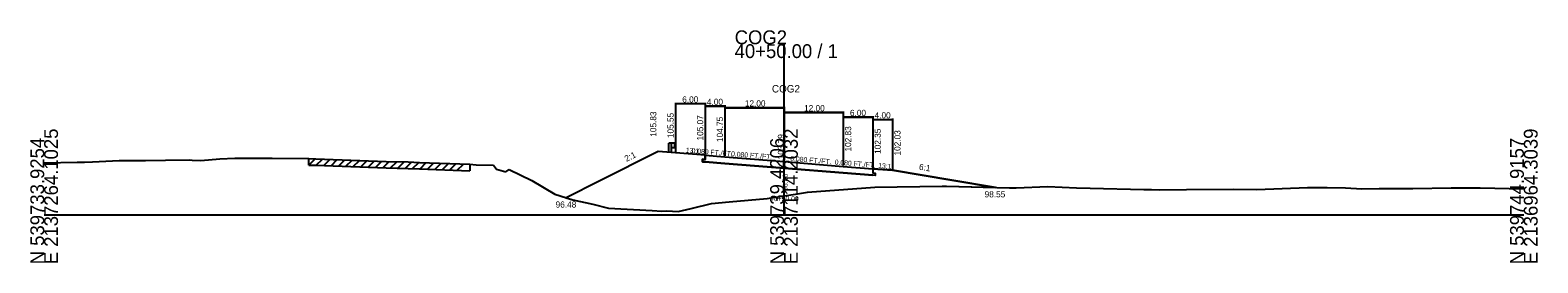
# Model space of a CAD drawing. Extents: x -13397 to 2303, y -10 to 39059.
# Drawn here: x 997.2 to 1302.8, y 20990.3 to 21037.4 of the extents above; entities that cross this region are included whole.
import ezdxf

# ---------------------------------------------------------------- set-up
doc = ezdxf.new("R2010")
doc.units = 0
for name, color, linetype in [('Level 1', 7, 'Continuous'), ('Level 5', 7, 'Continuous'), ('Level 53', 7, 'Continuous'), ('Level 54', 7, 'Continuous'), ('Level 55', 7, 'Continuous'), ('Level 7', 7, 'Continuous'), ('RD_GPK_XS_Cell', 7, 'Continuous'), ('RD_XS_EwShp', 7, 'Continuous'), ('RD_XS_ExGround', 7, 'Continuous'), ('RD_XS_ExPaveRet', 7, 'Continuous'), ('RD_XS_Pave', 7, 'Continuous'), ('RD_XS_TX_Baseline', 7, 'Continuous'), ('RD_XS_TX_Elev_EX', 7, 'Continuous'), ('RD_XS_TX_Elev_PR', 7, 'Continuous'), ('RD_XS_TX_Station', 7, 'Continuous')]:
    doc.layers.add(name, color=color, linetype=linetype)

msp = doc.modelspace()

# ---------------------------------------------------------------- linework, layer by layer
at = {"layer": 'Level 1'}
for p, q in [((1126.66, 21012.55), (1126.66, 21014.54)), ((1127.22, 21014.54), (1126.66, 21014.54)), ((1127.22, 21012.55), (1127.22, 21014.54)), ((1127.77, 21014.54), (1127.22, 21014.54)), ((1127.77, 21013.57), (1127.22, 21013.57)), ((1127.77, 21014.54), (1127.77, 21013.57)), ((1127.85, 21014.46), (1127.77, 21014.48)), ((1127.85, 21013.64), (1127.77, 21013.63)), ((1127.84, 21014.13), (1127.84, 21013.97)), ((1127.98, 21014.37), (1127.86, 21014.46)), ((1127.98, 21014.27), (1127.86, 21014.17)), ((1127.98, 21013.84), (1127.86, 21013.93)), ((1127.98, 21013.74), (1127.86, 21013.64))]:
    msp.add_line(p, q, dxfattribs=at)
for centre, radius, start, end in [((1127.91, 21014.13), 0.0651, 135, 180), ((1127.91, 21013.97), 0.0651, 180, 237.0105), ((1127.85, 21014.44), 0.026, 50.9495, 90), ((1127.85, 21013.66), 0.026, 270, 309.0504), ((1127.93, 21014.32), 0.0651, 309.0337, 50.9664), ((1127.93, 21013.79), 0.0651, 309.0337, 50.9664)]:
    msp.add_arc(centre, radius, start, end, dxfattribs=at)
at = {"layer": 'Level 5'}
for p, q in [((1133.5, 21011.28), (1133.5, 21010.78)), ((1134, 21011.24), (1133.5, 21011.28)), ((1133.5, 21010.78), (1134, 21010.74)), ((1134, 21012.07), (1134, 21011.24)), ((1138, 21010.42), (1134, 21010.74)), ((1138, 21010.42), (1134, 21010.74)), ((1138, 21010.42), (1134, 21010.74)), ((1134, 21010.74), (1138, 21010.42)), ((1150, 21009.46), (1138, 21010.42)), ((1150, 21009.46), (1138, 21010.42)), ((1150, 21009.46), (1138, 21010.42)), ((1138, 21010.42), (1150, 21009.46)), ((1138, 21010.42), (1150, 21009.46)), ((1162, 21008.5), (1150, 21009.46)), ((1162, 21008.5), (1150, 21009.46)), ((1150, 21009.46), (1162, 21008.5)), ((1150, 21009.46), (1162, 21008.5)), ((1150, 21009.46), (1162, 21008.5)), ((1168, 21008.02), (1162, 21008.5)), ((1162, 21008.5), (1168, 21008.02)), ((1162, 21008.5), (1168, 21008.02)), ((1162, 21008.5), (1168, 21008.02)), ((1168, 21009.35), (1168, 21008.52)), ((1168, 21008.52), (1168.5, 21008.48)), ((1168.5, 21007.98), (1168, 21008.02)), ((1168.5, 21008.48), (1168.5, 21007.98))]:
    msp.add_line(p, q, dxfattribs=at)
at = {"layer": 'Level 54'}
for p, q in [((1128, 21022.7), (1128, 21012.75)), ((1134, 21022.5), (1128, 21022.5)), ((1134, 21022.7), (1134, 21012.27)), ((1134, 21022.22), (1134, 21012.27)), ((1134, 21022.22), (1134, 21012.27)), ((1134, 21022.22), (1134, 21012.27)), ((1134, 21022.22), (1134, 21012.27)), ((1134, 21022.02), (1138, 21022.02)), ((1134, 21022.02), (1138, 21022.02)), ((1134, 21022.02), (1138, 21022.02)), ((1138, 21022.02), (1134, 21022.02)), ((1138, 21022.22), (1138, 21011.95)), ((1138, 21022.22), (1138, 21011.95)), ((1138, 21022.22), (1138, 21011.95)), ((1138, 21022.22), (1138, 21011.95)), ((1138, 21021.9), (1138, 21011.95)), ((1138, 21021.9), (1138, 21011.95)), ((1138, 21021.9), (1138, 21011.95)), ((1138, 21021.9), (1138, 21011.95)), ((1138, 21021.9), (1138, 21011.95)), ((1150, 21021.9), (1150, 21010.99)), ((1150, 21021.9), (1150, 21010.99)), ((1150, 21021.9), (1150, 21010.99)), ((1150, 21021.9), (1150, 21010.99)), ((1150, 21021.9), (1150, 21010.99)), ((1138, 21021.7), (1150, 21021.7)), ((1138, 21021.7), (1150, 21021.7)), ((1138, 21021.7), (1150, 21021.7)), ((1150, 21021.7), (1138, 21021.7)), ((1150, 21021.7), (1138, 21021.7)), ((1150, 21020.94), (1150, 21010.99)), ((1150, 21020.94), (1150, 21010.99)), ((1150, 21020.94), (1150, 21010.99)), ((1150, 21020.94), (1150, 21010.99)), ((1150, 21020.94), (1150, 21010.99)), ((1150, 21020.74), (1162, 21020.74)), ((1150, 21020.74), (1162, 21020.74)), ((1162, 21020.74), (1150, 21020.74)), ((1162, 21020.74), (1150, 21020.74)), ((1162, 21020.74), (1150, 21020.74)), ((1162, 21020.94), (1162, 21010.03)), ((1162, 21020.94), (1162, 21010.03)), ((1162, 21020.94), (1162, 21010.03)), ((1162, 21020.94), (1162, 21010.03)), ((1162, 21020.94), (1162, 21010.03)), ((1162, 21019.98), (1162, 21010.03)), ((1162, 21019.98), (1162, 21010.03)), ((1162, 21019.98), (1162, 21010.03)), ((1162, 21019.98), (1162, 21010.03)), ((1162, 21019.78), (1168, 21019.78)), ((1168, 21019.78), (1162, 21019.78)), ((1168, 21019.78), (1162, 21019.78)), ((1168, 21019.78), (1162, 21019.78)), ((1168, 21019.98), (1168, 21009.55)), ((1168, 21019.98), (1168, 21009.55)), ((1168, 21019.98), (1168, 21009.55)), ((1168, 21019.98), (1168, 21009.55)), ((1168, 21019.5), (1168, 21009.55)), ((1168, 21019.3), (1172, 21019.3)), ((1172, 21019.5), (1172, 21009.23))]:
    msp.add_line(p, q, dxfattribs=at)
at = {"layer": 'Level 7'}
for p, q in [((1124.5, 21012.83), (1112.5, 21006.83)), ((1128, 21012.55), (1124.5, 21012.83)), ((1134, 21012.07), (1128, 21012.55)), ((1112.5, 21006.83), (1105.81, 21003.48)), ((1168, 21009.35), (1172, 21009.03)), ((1172, 21009.03), (1184, 21007.03)), ((1184, 21007.03), (1192.87, 21005.55))]:
    msp.add_line(p, q, dxfattribs=at)
at = {"layer": 'RD_GPK_XS_Cell'}
for p, q in [((1150, 21000), (1150, 21034.56)), ((1000, 21000), (1150, 21000)), ((1150, 21000), (1300, 21000))]:
    msp.add_line(p, q, dxfattribs=at)
at = {"layer": 'RD_XS_EwShp'}
msp.add_lwpolyline([(1105.81, 21003.48), (1107.2, 21003.04), (1111.27, 21002.16), (1114.45, 21001.37), (1123.3, 21000.92), (1125.26, 21000.76), (1126.25, 21000.81), (1128.55, 21000.69), (1131.2, 21001.28), (1135.3, 21002.29), (1138.87, 21002.62), (1146.61, 21003.34), (1150, 21003.86), (1152.31, 21004.2), (1154.78, 21004.58), (1168.42, 21005.63), (1182.05, 21005.85), (1182.96, 21005.82), (1192.87, 21005.55), (1184, 21007.03), (1172, 21009.03), (1168, 21009.35), (1168, 21008.52), (1168.5, 21008.48), (1168.5, 21007.98), (1168, 21008.02), (1162, 21008.5), (1150, 21009.46), (1138, 21010.42), (1134, 21010.74), (1133.5, 21010.78), (1133.5, 21011.28), (1134, 21011.24), (1134, 21012.07), (1128, 21012.55), (1124.5, 21012.83), (1112.5, 21006.83)], close=True, dxfattribs=at)
at = {"layer": 'RD_XS_ExGround'}
for p, q in [((1000, 21010.54), (1006.68, 21010.66)), ((1006.68, 21010.66), (1008.21, 21010.68)), ((1008.21, 21010.68), (1009.79, 21010.77)), ((1009.79, 21010.77), (1015.23, 21011.05)), ((1015.23, 21011.05), (1020.52, 21011.02)), ((1020.52, 21011.02), (1024.59, 21011.07)), ((1024.59, 21011.07), (1029.47, 21011.17)), ((1029.47, 21011.17), (1030.03, 21011.09)), ((1030.03, 21011.09), (1031.78, 21011.04)), ((1031.78, 21011.04), (1035.64, 21011.37)), ((1035.64, 21011.37), (1038.67, 21011.46)), ((1038.67, 21011.46), (1043.48, 21011.52)), ((1043.48, 21011.52), (1046.23, 21011.49)), ((1046.23, 21011.49), (1053.66, 21011.4)), ((1053.66, 21011.4), (1055.1, 21011.35)), ((1055.1, 21011.35), (1056.81, 21011.29)), ((1056.81, 21011.29), (1069.31, 21010.84)), ((1069.31, 21010.84), (1073.77, 21010.72)), ((1073.77, 21010.72), (1076.11, 21010.64)), ((1076.11, 21010.64), (1086.29, 21010.25)), ((1086.29, 21010.25), (1087.62, 21010.17)), ((1087.62, 21010.17), (1091.13, 21010.04)), ((1091.13, 21010.04), (1091.73, 21009.24)), ((1091.73, 21009.24), (1093.62, 21008.75)), ((1093.62, 21008.75), (1094.26, 21009.17)), ((1094.26, 21009.17), (1098.86, 21006.97)), ((1098.86, 21006.97), (1103.53, 21004.21)), ((1103.53, 21004.21), (1107.2, 21003.04)), ((1146.61, 21003.34), (1150, 21003.86)), ((1150, 21003.86), (1152.31, 21004.2)), ((1152.31, 21004.2), (1154.78, 21004.58)), ((1154.78, 21004.58), (1168.42, 21005.63)), ((1168.42, 21005.63), (1182.05, 21005.85)), ((1182.05, 21005.85), (1182.96, 21005.82)), ((1182.96, 21005.82), (1195.69, 21005.48)), ((1195.69, 21005.48), (1197.05, 21005.47)), ((1197.05, 21005.47), (1203.49, 21005.77)), ((1203.49, 21005.77), (1209.33, 21005.5)), ((1209.33, 21005.5), (1212.04, 21005.41)), ((1212.04, 21005.41), (1222.96, 21005.18)), ((1222.96, 21005.18), (1224.48, 21005.14)), ((1224.48, 21005.14), (1226.06, 21005.1)), ((1226.06, 21005.1), (1231.6, 21005.15)), ((1231.6, 21005.15), (1241.05, 21005.2)), ((1241.05, 21005.2), (1245.89, 21005.17)), ((1245.89, 21005.17), (1256.11, 21005.55)), ((1256.11, 21005.55), (1260.14, 21005.54)), ((1260.14, 21005.54), (1263.87, 21005.47)), ((1263.87, 21005.47), (1267.14, 21005.28)), ((1267.14, 21005.28), (1270.67, 21005.37)), ((1270.67, 21005.37), (1274.22, 21005.38)), ((1274.22, 21005.38), (1277.51, 21005.36)), ((1277.51, 21005.36), (1285.24, 21005.46)), ((1285.24, 21005.46), (1288.38, 21005.48)), ((1288.38, 21005.48), (1291.15, 21005.5)), ((1291.15, 21005.5), (1300, 21005.25)), ((1107.2, 21003.04), (1111.27, 21002.16)), ((1111.27, 21002.16), (1114.45, 21001.37)), ((1114.45, 21001.37), (1123.3, 21000.92)), ((1123.3, 21000.92), (1125.26, 21000.76)), ((1125.26, 21000.76), (1126.25, 21000.81)), ((1126.25, 21000.81), (1128.55, 21000.69)), ((1128.55, 21000.69), (1131.2, 21001.28)), ((1131.2, 21001.28), (1135.3, 21002.29)), ((1135.3, 21002.29), (1138.87, 21002.62)), ((1138.87, 21002.62), (1146.61, 21003.34))]:
    msp.add_line(p, q, dxfattribs=at)
at = {"layer": 'RD_XS_ExPaveRet'}
for p, q in [((1053.66, 21010.1), (1053.66, 21011.4)), ((1053.66, 21010.1), (1054.92, 21011.36)), ((1053.66, 21010.1), (1055.1, 21010.05)), ((1055.1, 21010.05), (1056.81, 21009.99)), ((1055.17, 21010.05), (1056.42, 21011.31)), ((1056.67, 21010), (1057.93, 21011.25)), ((1056.81, 21009.99), (1069.31, 21009.54)), ((1058.17, 21009.94), (1059.43, 21011.2)), ((1059.68, 21009.89), (1060.94, 21011.14)), ((1061.18, 21009.84), (1062.44, 21011.09)), ((1062.68, 21009.78), (1063.94, 21011.04)), ((1064.19, 21009.73), (1065.45, 21010.98)), ((1065.69, 21009.67), (1066.95, 21010.93)), ((1067.19, 21009.62), (1068.45, 21010.88)), ((1068.7, 21009.57), (1069.96, 21010.83)), ((1069.31, 21009.54), (1073.77, 21009.42)), ((1070.2, 21009.52), (1071.47, 21010.78)), ((1071.7, 21009.48), (1072.97, 21010.74)), ((1073.21, 21009.43), (1074.47, 21010.69)), ((1074.71, 21009.38), (1075.97, 21010.64)), ((1076.21, 21009.33), (1077.47, 21010.59)), ((1077.72, 21009.28), (1078.97, 21010.53)), ((1079.22, 21009.22), (1080.48, 21010.47)), ((1080.72, 21009.16), (1081.98, 21010.42)), ((1082.23, 21009.11), (1083.48, 21010.36)), ((1083.73, 21009.05), (1084.99, 21010.3)), ((1086.29, 21010.25), (1086.29, 21008.95)), ((1073.77, 21009.42), (1076.11, 21009.34)), ((1076.11, 21009.34), (1086.29, 21008.95))]:
    msp.add_line(p, q, dxfattribs=at)
at = {"layer": 'RD_XS_Pave'}
for p, q in [((1134, 21012.07), (1138, 21011.75)), ((1138, 21011.75), (1150, 21010.79)), ((1150, 21010.79), (1162, 21009.83)), ((1162, 21009.83), (1168, 21009.35))]:
    msp.add_line(p, q, dxfattribs=at)

# ---------------------------------------------------------------- texts
at = {"layer": 'Level 53'}
for s, rotation, p in [('105.83', 90, (1124.12, 21015.83)), ('105.55', 90, (1127.62, 21015.55)), ('105.07', 90, (1133.62, 21015.07)), ('104.75', 90, (1137.62, 21014.75)), ('104.75', 90, (1137.62, 21014.75)), ('104.75', 90, (1137.62, 21014.75)), ('102.83', 90, (1163.62, 21012.83)), ('102.83', 90, (1163.62, 21012.83)), ('102.83', 90, (1163.62, 21012.83)), ('102.35', 90, (1169.62, 21012.35)), ('102.03', 90, (1173.62, 21012.03)), ('2:1', 26.5651, (1118.05, 21010.72)), ('6:1', 350.5377, (1177.3, 21009.16))]:
    msp.add_text(s, height=1.25, rotation=rotation, dxfattribs=at).set_placement(p)
for s, p in [('98.55', (1190.68, 21003.55)), ('96.48', (1103.7, 21001.48))]:
    msp.add_text(s, height=1.25, dxfattribs=at).set_placement(p)
at = {"layer": 'Level 54'}
for s, p in [('6.00', (1129.37, 21022.75)), ('4.00', (1134.37, 21022.27)), ('4.00', (1134.37, 21022.27)), ('4.00', (1134.37, 21022.27)), ('4.00', (1134.37, 21022.27)), ('12.00', (1142.07, 21021.95)), ('12.00', (1142.07, 21021.95)), ('12.00', (1142.07, 21021.95)), ('12.00', (1142.07, 21021.95)), ('12.00', (1142.07, 21021.95)), ('12.00', (1154.07, 21020.99)), ('12.00', (1154.07, 21020.99)), ('12.00', (1154.07, 21020.99)), ('12.00', (1154.07, 21020.99)), ('12.00', (1154.07, 21020.99)), ('6.00', (1163.37, 21020.03)), ('6.00', (1163.37, 21020.03)), ('6.00', (1163.37, 21020.03)), ('6.00', (1163.37, 21020.03)), ('4.00', (1168.37, 21019.55))]:
    msp.add_text(s, height=1.25, dxfattribs=at).set_placement(p)
at = {"layer": 'Level 55'}
for s, p in [('13:1', (1130.07, 21012.64)), ('0.080 FT./FT.', (1131.24, 21012.54)), ('0.080 FT./FT.', (1131.24, 21012.54)), ('0.080 FT./FT.', (1131.24, 21012.54)), ('0.080 FT./FT.', (1131.24, 21012.54)), ('0.080 FT./FT.', (1139.24, 21011.9)), ('0.080 FT./FT.', (1139.24, 21011.9)), ('0.080 FT./FT.', (1139.24, 21011.9)), ('0.080 FT./FT.', (1139.24, 21011.9)), ('0.080 FT./FT.', (1139.24, 21011.9)), ('0.080 FT./FT.', (1151.24, 21010.94)), ('0.080 FT./FT.', (1151.24, 21010.94)), ('0.080 FT./FT.', (1151.24, 21010.94)), ('0.080 FT./FT.', (1151.24, 21010.94)), ('0.080 FT./FT.', (1151.24, 21010.94)), ('0.080 FT./FT.', (1160.24, 21010.22)), ('0.080 FT./FT.', (1160.24, 21010.22)), ('0.080 FT./FT.', (1160.24, 21010.22)), ('0.080 FT./FT.', (1160.24, 21010.22)), ('13:1', (1169.07, 21009.52))]:
    msp.add_text(s, height=1, rotation=355.4261, dxfattribs=at).set_placement(p)
at = {"layer": 'RD_GPK_XS_Cell'}
for s, p in [('COG2', (1140, 21034.56)), ('40+50.00 / 1', (1140, 21031.76))]:
    msp.add_text(s, height=2.8, dxfattribs=at).set_placement(p)
for s, p in [('E 2137264.1025', (1002.8, 20990)), ('E 2137114.2032', (1152.8, 20990)), ('E 2136964.3039', (1302.8, 20990)), ('N 539733.9254', (1000, 20990)), ('N 539739.4206', (1150, 20990)), ('N 539744.9157', (1300, 20990))]:
    msp.add_text(s, height=2.8, rotation=90, dxfattribs=at).set_placement(p)
at = {"layer": 'RD_XS_TX_Baseline'}
msp.add_text('COG2', height=1.5, dxfattribs=at).set_placement((1147.55, 21024.79))
at = {"layer": 'RD_XS_TX_Elev_EX'}
msp.add_text('96.86', height=1, rotation=90, dxfattribs=at).set_placement((1150.75, 21004.86))
at = {"layer": 'RD_XS_TX_Elev_PR'}
msp.add_text(' 103.79', height=1.25, rotation=90, dxfattribs=at).set_placement((1150, 21010.79))
at = {"layer": 'RD_XS_TX_Station'}
msp.add_text('40+50.00', height=1, dxfattribs=at).set_placement((1147.19, 21002.79))

doc.saveas('drawing.dxf')
